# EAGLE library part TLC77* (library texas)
MICROPOWER SUPPLY VOLTAGE SUPERVISORS Source: www.ti.com/.. slvs087l.pdf
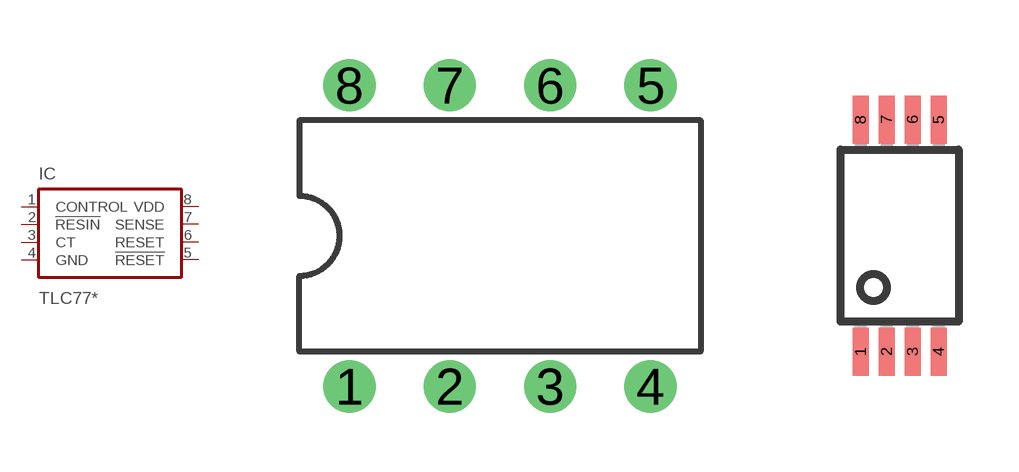
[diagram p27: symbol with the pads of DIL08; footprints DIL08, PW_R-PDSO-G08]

Designator prefix IC

## TLC7701D (OC_FARNELL: unknown; OC_NEWARK: unknown), TLC7703D (MF: TEXAS INSTRUMENT CONNECTORS; MPN: TLC7703QPE4; OC_FARNELL: unknown; OC_NEWARK: 24K5359), TLC7705D (MF: TEXAS INSTRUMENT CONNECTORS; MPN: TLC7705QP; OC_FARNELL: 8454671; OC_NEWARK: 76C7537), TLC7725D (MF: TEXAS INSTRUMENT CONNECTORS; MPN: TLC7725QP; OC_FARNELL: unknown; OC_NEWARK: 76C7546), TLC7733D (MF: TEXAS INSTRUMENT CONNECTORS; MPN: TLC7733QP; OC_FARNELL: 1411422; OC_NEWARK: 76C7553)  [DIL08]
1  CONTROL  in
2  !RESIN  in
3  CT  in
4  GND  pwr
5  !RESET  out
6  RESET  out
7  SENSE  in
8  VDD  pwr

## TLC7701PW (MF: TEXAS INSTRUMENTS; MPN: TLC7701IPWR; OC_FARNELL: 1461368; OC_NEWARK: 76C7519), TLC7703PW (MF: TEXAS INSTRUMENT CONNECTORS; MPN: TLC7703IPW; OC_FARNELL: 1411411; OC_NEWARK: 76C7527), TLC7705PW (MF: TEXAS INSTRUMENT CONNECTORS; MPN: TLC7705QPW; OC_FARNELL: 1411414; OC_NEWARK: 95H4505), TLC7725PW (MPN: TLC7725IPWG4; OC_FARNELL: 1411418; OC_NEWARK: 18M3172), TLC7733PW (MPN: TLC7733QPWG4; OC_FARNELL: 1411423; OC_NEWARK: 54K1054)  [PW_R-PDSO-G08]
Pads as for DIL08

## TLC7701FK (OC_FARNELL: unknown; OC_NEWARK: unknown), TLC7703FK (OC_FARNELL: unknown; OC_NEWARK: unknown), TLC7705FK (OC_FARNELL: unknown; OC_NEWARK: unknown), TLC7725FK (OC_FARNELL: unknown; OC_NEWARK: unknown), TLC7733FK (OC_FARNELL: unknown; OC_NEWARK: unknown)  [PLCC20]
1  CONTROL  in
5  !RESIN  in
7  CT  in
10  GND  pwr
12  !RESET  out
15  RESET  out
17  SENSE  in
20  VDD  pwr

## TLC7701P (MF: TEXAS INSTRUMENT CONNECTORS; MPN: TLC7701IP; OC_FARNELL: 1411405; OC_NEWARK: 76C7517), TLC7703P (MF: TEXAS INSTRUMENT CONNECTORS; MPN: TLC7703QP; OC_FARNELL: 1287644; OC_NEWARK: 76C7531), TLC7705P (MF: TEXAS INSTRUMENT CONNECTORS; MPN: TLC7705IP; OC_FARNELL: 1510448; OC_NEWARK: 35K1227), TLC7725P (MF: TEXAS INSTRUMENT CONNECTORS; MPN: TLC7725IP; OC_FARNELL: unknown; OC_NEWARK: 76C7541), TLC7733P (MF: TEXAS INSTRUMENT CONNECTORS; MPN: TLC7733QP; OC_FARNELL: 1411422; OC_NEWARK: 76C7553)  [DIL08]
Pads as for DIL08

## Footprint DIL08 (pad centres in mm)
Dual In Line Package
drill 0.813 pad 1.27 round: 1 -3.81,-3.81; 2 -1.27,-3.81; 3 1.27,-3.81; 4 3.81,-3.81; 5 3.81,3.81; 6 1.27,3.81; 7 -1.27,3.81; 8 -3.81,3.81

## Footprint PW_R-PDSO-G08 (pad centres in mm)
PLASTIC SMALL-OUTLINE PACKAGE, SO 8 JEDEC MO-153, PW Type Source: www.ti.com/.. slvs087l.pdf
smd 0.4 x 1.2: 1 -0.975,-2.9; 2 -0.325,-2.9; 3 0.325,-2.9; 4 0.975,-2.9; 5 0.975,2.9; 6 0.325,2.9; 7 -0.325,2.9; 8 -0.975,2.9

## Footprint PLCC20 (pad centres in mm)
Plastic Leaded Chip Carrier
smd 0.6 x 2.2: 1 0,4.3; 2 -1.27,4.3; 3 -2.54,4.3; 9 -2.54,-4.3; 10 -1.27,-4.3; 11 0,-4.3; 12 1.27,-4.3; 13 2.54,-4.3; 19 2.54,4.3; 20 1.27,4.3
smd 2.2 x 0.6: 4 -4.3,2.54; 5 -4.3,1.27; 6 -4.3,0; 7 -4.3,-1.27; 8 -4.3,-2.54; 14 4.3,-2.54; 15 4.3,-1.27; 16 4.3,0; 17 4.3,1.27; 18 4.3,2.54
